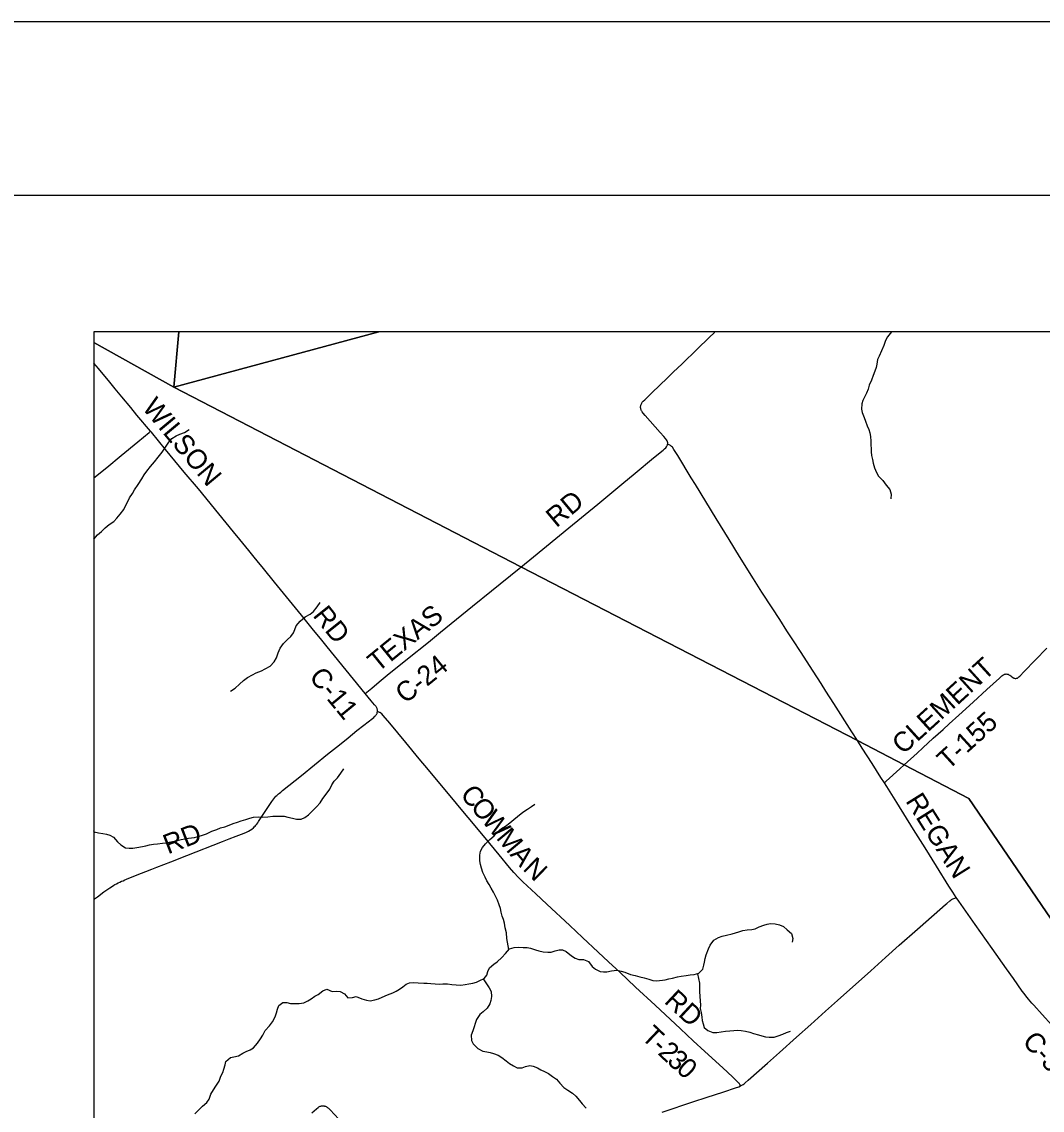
# Model space of a CAD drawing. Extents: x 0 to 34, y 0 to 22.
# Drawn here: x 24.58 to 27.52, y 18.863 to 22 of the extents above; entities that cross this region are included whole.
import ezdxf

# ---------------------------------------------------------------- set-up
doc = ezdxf.new("R2010")
doc.units = 0
for name, color, linetype in [('GM_X_Corporation', 7, 'Continuous'), ('GM_X_County_Road', 7, 'Continuous'), ('GM_X_County_Road_Text', 7, 'Continuous'), ('GM_X_Minor_River', 7, 'Continuous'), ('GM_X_Township_Road', 7, 'Continuous'), ('GM_X_Township_Road_Text', 7, 'Continuous'), ('SH_Border', 7, 'Continuous'), ('SH_Cut_Line', 7, 'Continuous')]:
    doc.layers.add(name, color=color, linetype=linetype)

msp = doc.modelspace()

# ---------------------------------------------------------------- linework, layer by layer
at = {"layer": 'GM_X_Corporation'}
for points in [[(31.5875, 16.2767), (31.5875, 21.1059), (24.7875, 21.1059), (24.7875, 14.3059), (28.9316, 14.3059), (29.0116, 14.3654), (30.2271, 15.2782), (30.4064, 15.4161), (30.5426, 15.5161)], [(25.0317, 21.1059), (24.7875, 21.1059), (24.7875, 21.0754), (25.0178, 20.9472)], [(31.5875, 16.2767), (31.5875, 21.1059), (25.6086, 21.1059), (25.0178, 20.9472), (26.0175, 20.4289), (26.9873, 19.9283), (27.122, 19.8586), (27.3085, 19.7612), (27.7955, 19.0474), (28.3618, 18.3058), (29.4482, 16.7745), (29.7308, 16.376), (30.2965, 15.5727), (30.4064, 15.4161), (30.5426, 15.5161)], [(25.6086, 21.1059), (25.0317, 21.1059), (25.0178, 20.9472)], [(24.7875, 21.0754), (24.7875, 14.3059), (28.9316, 14.3059), (29.0116, 14.3654), (30.2271, 15.2782), (30.4064, 15.4161), (30.2965, 15.5727), (29.7308, 16.376), (29.4482, 16.7745), (28.3618, 18.3058), (27.7955, 19.0474), (27.3085, 19.7612), (27.122, 19.8586), (26.9873, 19.9283), (26.0175, 20.4289), (25.0178, 20.9472)]]:
    msp.add_lwpolyline(points, close=True, dxfattribs=at)
at = {"layer": 'GM_X_County_Road'}
for points in [[(26.4403, 20.7819), (26.4406, 20.7839), (26.4406, 20.785), (26.4406, 20.7868), (26.4403, 20.7885), (26.4398, 20.7904), (26.4388, 20.7925), (26.4373, 20.7948), (26.4344, 20.7987), (26.4295, 20.8043), (26.4188, 20.8165), (26.4049, 20.8324), (26.3755, 20.8652), (26.3701, 20.8714), (26.3672, 20.8755), (26.3662, 20.8772), (26.3652, 20.8788), (26.3646, 20.8803), (26.364, 20.8817), (26.3632, 20.8837), (26.3629, 20.8855), (26.3626, 20.888), (26.3626, 20.8895), (26.3626, 20.8913), (26.3629, 20.8931), (26.3632, 20.8944), (26.3639, 20.8969), (26.3648, 20.8986), (26.3657, 20.9004), (26.3665, 20.9017), (26.3674, 20.9031), (26.3699, 20.906), (26.3744, 20.9105), (26.3872, 20.9231), (26.3975, 20.933), (26.4151, 20.9496), (26.4415, 20.9751), (26.4565, 20.9899), (26.4822, 21.0143), (26.5259, 21.0567), (26.5596, 21.0897), (26.5753, 21.1048), (26.5764, 21.1059)], [(24.9507, 20.8198), (24.9115, 20.8663), (24.8935, 20.8885), (24.868, 20.919), (24.8491, 20.9421), (24.8336, 20.9607), (24.8008, 21.0005), (24.7875, 21.0162)], [(25.5692, 20.0641), (25.5357, 20.1054), (25.4598, 20.1983), (25.444, 20.2175), (25.4159, 20.2515), (25.3853, 20.2899), (25.3509, 20.3316), (25.3078, 20.3846), (25.276, 20.4236), (25.2581, 20.4459), (25.2495, 20.4565), (25.2336, 20.4756), (25.2075, 20.5073), (25.1892, 20.53), (25.1473, 20.5816), (25.0887, 20.6533), (25.0479, 20.7018), (25.0345, 20.7181), (24.9936, 20.7673), (24.9532, 20.8169), (24.9507, 20.8198)], [(26.0177, 20.4283), (26.0539, 20.4581), (26.1561, 20.5412), (26.239, 20.6096), (26.3086, 20.6669), (26.3472, 20.6991), (26.3998, 20.7427), (26.4271, 20.7653), (26.4317, 20.7693), (26.4348, 20.7723), (26.4371, 20.7752), (26.4381, 20.7768), (26.4389, 20.7783), (26.4398, 20.7804), (26.4403, 20.7819)], [(26.9875, 19.9278), (26.9711, 19.9535), (26.9193, 20.0347), (26.896, 20.0707), (26.8823, 20.0922), (26.8593, 20.1284), (26.8234, 20.1844), (26.8035, 20.2152), (26.784, 20.2447), (26.7632, 20.2772), (26.7412, 20.311), (26.7117, 20.3563), (26.6877, 20.3941), (26.6478, 20.4585), (26.6177, 20.5079), (26.5806, 20.5682), (26.5205, 20.6662), (26.5084, 20.6857), (26.4697, 20.7495), (26.4584, 20.7674), (26.454, 20.7739), (26.452, 20.7761), (26.4498, 20.7777), (26.4482, 20.7788), (26.4469, 20.7794), (26.445, 20.7801), (26.4403, 20.7819)], [(25.5692, 20.0641), (25.5881, 20.0795), (25.609, 20.0974), (25.632, 20.1163), (25.6906, 20.1634), (25.7511, 20.2121), (25.7857, 20.2404), (25.8784, 20.3156), (25.9325, 20.3593), (26.0122, 20.4238), (26.0177, 20.4283)], [(25.6041, 20.0116), (25.6042, 20.0168), (25.6038, 20.0186), (25.6032, 20.0202), (25.6024, 20.0223), (25.6014, 20.024), (25.6004, 20.0255), (25.5994, 20.027), (25.5962, 20.0315), (25.5867, 20.0424), (25.5692, 20.0641)], [(24.7875, 19.4705), (24.7919, 19.4738), (24.7974, 19.4781), (24.816, 19.4916), (24.8333, 19.5037), (24.8412, 19.5088), (24.8449, 19.511), (24.8482, 19.5129), (24.8529, 19.5154), (24.857, 19.5176), (24.862, 19.5199), (24.8672, 19.5224), (24.8713, 19.5241), (24.8764, 19.5263), (24.8815, 19.5285), (24.9069, 19.5387), (24.9542, 19.5574), (24.9686, 19.5632), (25.0092, 19.579), (25.0548, 19.597), (25.1584, 19.6374), (25.1776, 19.6446), (25.1974, 19.6521), (25.213, 19.6583), (25.2255, 19.6635), (25.2289, 19.6651), (25.2328, 19.667), (25.2381, 19.6701), (25.2422, 19.6728), (25.247, 19.6765), (25.2495, 19.679), (25.2518, 19.6813), (25.2543, 19.6843), (25.2565, 19.6869), (25.2594, 19.691), (25.2618, 19.6945), (25.2903, 19.7383), (25.2999, 19.7528), (25.3054, 19.7603), (25.3086, 19.7639), (25.3117, 19.7674), (25.3146, 19.7701), (25.3164, 19.7717), (25.319, 19.7742), (25.322, 19.7767), (25.3256, 19.7797), (25.331, 19.7841), (25.3852, 19.8278), (25.4608, 19.8884), (25.4946, 19.9158), (25.5197, 19.9362), (25.5453, 19.9568), (25.5653, 19.9727), (25.5897, 19.9919), (25.5935, 19.995), (25.5972, 19.9983), (25.5986, 19.9997), (25.6001, 20.0014), (25.6016, 20.0033), (25.6024, 20.0047), (25.6032, 20.0065), (25.6039, 20.0087), (25.6041, 20.0116)], [(27.0648, 19.8064), (27.0549, 19.822), (27.0293, 19.8624), (27.0012, 19.9064), (26.9875, 19.9278)], [(27.2719, 19.4757), (27.2618, 19.4911), (27.2504, 19.5088), (27.2148, 19.5665), (27.1823, 19.6187), (27.1492, 19.6713), (27.1006, 19.7494), (27.072, 19.7953), (27.0648, 19.8064)], [(27.6884, 18.9512), (27.6794, 18.9612), (27.6446, 19), (27.6128, 19.035), (27.5895, 19.0608), (27.5681, 19.0842), (27.5474, 19.1073), (27.5192, 19.138), (27.4952, 19.165), (27.4895, 19.1714), (27.4847, 19.177), (27.4802, 19.1823), (27.4762, 19.1874), (27.4722, 19.1925), (27.4673, 19.1992), (27.4623, 19.206), (27.4369, 19.242), (27.4167, 19.2704), (27.3758, 19.3283), (27.3261, 19.3981), (27.2789, 19.4652), (27.2719, 19.4757)]]:
    msp.add_lwpolyline(points, dxfattribs=at)
at = {"layer": 'GM_X_Minor_River'}
for points in [[(27.0857, 21.1059), (27.0812, 21.1017), (27.0742, 21.0915), (27.068, 21.0809), (27.0629, 21.0673), (27.0503, 21.0363), (27.0453, 21.0261), (27.0428, 21.0128), (27.0416, 21.0033), (27.0376, 20.9931), (27.0322, 20.9807), (27.0274, 20.967), (27.0212, 20.9527), (27.018, 20.9409), (27.0137, 20.9296), (27.009, 20.9197), (27.0031, 20.9084), (26.9996, 20.8986), (26.9987, 20.8834), (27.0008, 20.8739), (27.0064, 20.8597), (27.01, 20.8491), (27.0152, 20.8353), (27.02, 20.8246), (27.0233, 20.8151), (27.0251, 20.8041), (27.0257, 20.7915), (27.0259, 20.7797), (27.0266, 20.7698), (27.0265, 20.7603), (27.0279, 20.7501), (27.0304, 20.7383), (27.0322, 20.728), (27.0362, 20.7146), (27.0425, 20.7009), (27.0477, 20.6898), (27.0605, 20.6775), (27.0698, 20.6645), (27.0807, 20.6514), (27.0847, 20.6385), (27.0834, 20.6252)], [(24.9722, 20.7446), (24.9838, 20.7593), (24.9942, 20.7736), (25.0031, 20.788), (25.012, 20.7985), (25.0247, 20.806), (25.0346, 20.8108), (25.0488, 20.8163), (25.0622, 20.8249)], [(24.7875, 20.5086), (24.7983, 20.5209), (24.8091, 20.5306), (24.8195, 20.5415), (24.831, 20.5505), (24.8448, 20.5595), (24.854, 20.5693), (24.8629, 20.5806), (24.8734, 20.5945), (24.8796, 20.6066), (24.8854, 20.6168), (24.8901, 20.6274), (24.899, 20.6406), (24.9049, 20.6511), (24.9153, 20.6666), (24.9254, 20.6828), (24.9324, 20.6938), (24.9397, 20.7043), (24.9502, 20.7179), (24.9618, 20.7311), (24.9722, 20.7446)], [(25.1813, 20.0705), (25.1944, 20.0791), (25.2074, 20.0903), (25.2186, 20.1009), (25.2297, 20.1099), (25.2447, 20.118), (25.255, 20.1229), (25.2699, 20.1295), (25.281, 20.1351), (25.2952, 20.1425), (25.3064, 20.1546), (25.3134, 20.1667), (25.3185, 20.1814), (25.324, 20.1947), (25.3333, 20.2075), (25.3452, 20.2195), (25.3548, 20.2285), (25.3625, 20.2387), (25.3665, 20.2485), (25.37, 20.2591), (25.3816, 20.2719), (25.3958, 20.2843), (25.4104, 20.2929), (25.4204, 20.3), (25.4308, 20.3131), (25.4389, 20.326)], [(24.7884, 19.665), (24.8005, 19.6626), (24.8134, 19.6601), (24.8233, 19.6581), (24.8335, 19.6557), (24.8437, 19.6492), (24.8554, 19.6365), (24.8651, 19.6273), (24.8783, 19.6188), (24.889, 19.6179), (24.8993, 19.6178), (24.9115, 19.6199), (24.9275, 19.6228), (24.937, 19.6249), (24.9477, 19.6275), (24.9591, 19.6293), (24.9706, 19.6303), (24.985, 19.632), (24.9957, 19.633), (25.0087, 19.6359), (25.0186, 19.6385), (25.0384, 19.6428), (25.0495, 19.6453), (25.0598, 19.6467), (25.0769, 19.6488), (25.0911, 19.6525), (25.1006, 19.6554), (25.1117, 19.6591), (25.1277, 19.6665), (25.1415, 19.672), (25.1526, 19.6761), (25.1648, 19.6797), (25.177, 19.6842), (25.1885, 19.6886), (25.2011, 19.693), (25.2122, 19.6971), (25.2248, 19.7003), (25.2366, 19.7048), (25.2473, 19.7073), (25.2629, 19.7079), (25.2736, 19.7074), (25.2888, 19.7087), (25.3025, 19.7097), (25.3124, 19.7104), (25.3219, 19.7103), (25.3356, 19.7101), (25.3466, 19.7077), (25.3599, 19.7041), (25.3713, 19.7017), (25.3842, 19.7012), (25.3953, 19.7064), (25.4061, 19.7139), (25.4176, 19.7255), (25.4292, 19.7368), (25.4396, 19.7488), (25.4473, 19.7609), (25.457, 19.7733), (25.4671, 19.7884), (25.4725, 19.8009), (25.4795, 19.8107), (25.4888, 19.8209), (25.4992, 19.8337), (25.5073, 19.8469)], [(25.983, 19.3259), (25.9788, 19.3469), (25.977, 19.3576), (25.976, 19.3739), (25.9728, 19.3884), (25.9703, 19.4017), (25.9678, 19.412), (25.9641, 19.4223), (25.9612, 19.433), (25.9586, 19.4436), (25.955, 19.4547), (25.9498, 19.4677), (25.9446, 19.4799), (25.9387, 19.491), (25.9316, 19.5024), (25.926, 19.5131), (25.9197, 19.5242), (25.9148, 19.5346), (25.9081, 19.5479), (25.9037, 19.5601), (25.9012, 19.5708), (25.8994, 19.5818), (25.8992, 19.5974), (25.9017, 19.6088), (25.9067, 19.6201), (25.9156, 19.6303), (25.9283, 19.6427), (25.9406, 19.6539), (25.9495, 19.6641), (25.9622, 19.6746), (25.9737, 19.6813), (25.9856, 19.6914), (25.9971, 19.7008), (26.0083, 19.709), (26.0232, 19.7214), (26.037, 19.73), (26.0478, 19.7382), (26.0581, 19.7449)], [(24.7875, 19.6612), (24.7891, 19.6627), (24.7875, 19.6682)], [(25.7928, 19.2271), (25.8061, 19.2269), (25.8183, 19.2249), (25.8312, 19.2236), (25.8449, 19.2234), (25.8574, 19.2248), (25.8677, 19.2266), (25.8796, 19.2287), (25.8895, 19.232), (25.8994, 19.2361), (25.9121, 19.2424), (25.9194, 19.2522), (25.9226, 19.2624), (25.9273, 19.2734), (25.9396, 19.2839), (25.9495, 19.2899), (25.9623, 19.3026), (25.973, 19.3139), (25.9846, 19.3279), (25.998, 19.3315), (26.0117, 19.3321), (26.0242, 19.3316), (26.0356, 19.3315), (26.0451, 19.3295), (26.0599, 19.3247), (26.0698, 19.322), (26.0815, 19.3195), (26.0948, 19.3183), (26.1044, 19.3185), (26.1162, 19.3222), (26.128, 19.3247), (26.1375, 19.3246), (26.1477, 19.3203), (26.1636, 19.3072), (26.1738, 19.301), (26.1844, 19.2971), (26.1981, 19.2973), (26.2125, 19.2911), (26.2226, 19.2773), (26.2327, 19.2696), (26.2463, 19.2626), (26.2558, 19.261), (26.2654, 19.2616), (26.2787, 19.2641), (26.294, 19.2663), (26.3065, 19.2638), (26.3167, 19.2603), (26.3334, 19.254), (26.3466, 19.2505), (26.3607, 19.2473), (26.3732, 19.2445), (26.3865, 19.2401), (26.3975, 19.2366), (26.4096, 19.2357), (26.4332, 19.2385), (26.4443, 19.241), (26.4546, 19.2436), (26.4687, 19.2468), (26.4794, 19.2486), (26.4939, 19.2507), (26.5057, 19.2525), (26.5171, 19.2539), (26.5301, 19.2572), (26.5417, 19.2692), (26.5445, 19.2802), (26.5465, 19.2896), (26.5489, 19.2999), (26.5517, 19.3105), (26.558, 19.3275), (26.5634, 19.3388), (26.5739, 19.3528), (26.5865, 19.3606), (26.5976, 19.3639), (26.6098, 19.3668), (26.6262, 19.3712), (26.6358, 19.3737), (26.6457, 19.3771), (26.6568, 19.3807), (26.6694, 19.3825), (26.6831, 19.3839), (26.693, 19.3856), (26.7037, 19.3908), (26.7171, 19.3956), (26.7274, 19.3989), (26.7369, 19.4011), (26.7498, 19.4002), (26.7627, 19.3974), (26.7745, 19.3919), (26.785, 19.3823), (26.7971, 19.3716), (26.8011, 19.3578), (26.7994, 19.3468)], [(25.9088, 19.2408), (25.9187, 19.2272), (25.9266, 19.2153), (25.9318, 19.2046), (25.9331, 19.1905), (25.9315, 19.1788), (25.9283, 19.1689), (25.9205, 19.1565), (25.909, 19.146), (25.8994, 19.1381), (25.8901, 19.1245), (25.8861, 19.1128), (25.883, 19.103), (25.879, 19.0916), (25.8739, 19.0787), (25.8753, 19.0631), (25.8805, 19.0536), (25.8933, 19.0409), (25.908, 19.0328), (25.9194, 19.0304), (25.9293, 19.0287), (25.9391, 19.026), (25.9524, 19.0209), (25.9626, 19.0147), (25.975, 19.0047), (25.9852, 18.9969), (25.9965, 18.9904), (26.0067, 18.9845), (26.0216, 18.9844), (26.0311, 18.9885), (26.0433, 18.9917), (26.0532, 18.9897), (26.0653, 18.9847), (26.0751, 18.9792), (26.0861, 18.9738), (26.0971, 18.968), (26.1084, 18.9599), (26.1201, 18.9517), (26.1302, 18.9402), (26.1411, 18.9283), (26.1528, 18.9202), (26.1664, 18.9121), (26.1762, 18.9032), (26.1863, 18.891), (26.1938, 18.8806), (26.2058, 18.868)], [(26.526, 19.2561), (26.5292, 19.2427), (26.5321, 19.229), (26.5319, 19.2172), (26.5321, 19.2047), (26.5327, 19.1903), (26.5337, 19.1781), (26.5347, 19.1652), (26.5346, 19.1557), (26.5371, 19.1439), (26.5389, 19.1309), (26.5403, 19.1214), (26.5428, 19.1115), (26.5461, 19.1012), (26.5559, 19.0924), (26.571, 19.0869), (26.5825, 19.0867), (26.595, 19.0885), (26.6072, 19.0903), (26.6198, 19.0916), (26.6312, 19.0927), (26.6423, 19.0929), (26.6521, 19.092), (26.6647, 19.0904), (26.6772, 19.0872), (26.6878, 19.0837), (26.7026, 19.0797), (26.7121, 19.0769), (26.7227, 19.0742), (26.7329, 19.0729), (26.7478, 19.0735), (26.7593, 19.0772), (26.7719, 19.0816), (26.7833, 19.0868), (26.794, 19.0908)], [(25.0779, 18.8522), (25.0887, 18.8631), (25.1007, 18.8743), (25.1126, 18.8844), (25.1199, 18.8946), (25.1247, 18.9086), (25.132, 18.9218), (25.1383, 18.9316), (25.1479, 18.9463), (25.1531, 18.9603), (25.1593, 18.9713), (25.1621, 18.9811), (25.1656, 18.9932), (25.168, 19.0027), (25.1807, 19.0147), (25.1906, 19.0165), (25.204, 19.0198), (25.2166, 19.0269), (25.2266, 19.0321), (25.2373, 19.0369), (25.2473, 19.0425), (25.2588, 19.056), (25.267, 19.0685), (25.2743, 19.0786), (25.281, 19.0919), (25.2937, 19.1058), (25.3018, 19.1178), (25.3096, 19.1318), (25.3139, 19.1432), (25.3167, 19.1534), (25.3203, 19.164), (25.3322, 19.1726), (25.3432, 19.1732), (25.3542, 19.1701), (25.3698, 19.1706), (25.3793, 19.1705), (25.3919, 19.1719), (25.4034, 19.1775), (25.413, 19.1835), (25.4237, 19.1909), (25.4333, 19.1958), (25.4467, 19.2066), (25.4586, 19.2111), (25.4741, 19.2044), (25.4851, 19.2054), (25.4973, 19.2049), (25.509, 19.198), (25.5191, 19.1868), (25.5328, 19.1874), (25.5428, 19.1904), (25.5598, 19.1841), (25.5731, 19.1794), (25.5833, 19.1781), (25.5971, 19.1806), (25.6074, 19.1835), (25.6181, 19.1887), (25.633, 19.1947), (25.6483, 19.2013), (25.6579, 19.2062), (25.6678, 19.2114), (25.6774, 19.2185), (25.6874, 19.2263), (25.697, 19.23), (25.7091, 19.2303), (25.7221, 19.2297), (25.738, 19.2288), (25.7479, 19.2287), (25.7586, 19.2282), (25.7707, 19.2269), (25.7821, 19.2257), (25.7928, 19.2271)]]:
    msp.add_lwpolyline(points, dxfattribs=at)
at = {"layer": 'GM_X_Township_Road'}
for points in [[(24.7875, 20.6853), (24.8243, 20.7153), (24.8656, 20.7493), (24.9144, 20.7896), (24.9465, 20.8163), (24.9507, 20.8198)], [(27.1222, 19.8581), (27.1594, 19.8922), (27.176, 19.9072), (27.2056, 19.9347), (27.2338, 19.9601), (27.2518, 19.9763), (27.2793, 20.0015), (27.3207, 20.039), (27.3604, 20.0748), (27.3965, 20.1082), (27.4006, 20.112), (27.4034, 20.1145), (27.4057, 20.1162), (27.4079, 20.1177), (27.4096, 20.1187), (27.4114, 20.1194), (27.4134, 20.1198), (27.4151, 20.12), (27.4174, 20.1199), (27.4192, 20.1196), (27.4212, 20.119), (27.4234, 20.118), (27.4261, 20.1164), (27.4291, 20.1143), (27.4325, 20.1115), (27.4365, 20.1087), (27.4379, 20.108), (27.4393, 20.1075), (27.4412, 20.1072), (27.4424, 20.1072), (27.4438, 20.1071), (27.4454, 20.1075), (27.4468, 20.1078), (27.448, 20.1084), (27.4494, 20.1093), (27.4524, 20.1116), (27.4547, 20.1136), (27.4675, 20.1272), (27.4996, 20.1602), (27.5331, 20.1943)], [(26.6505, 18.9328), (26.6499, 18.9342), (26.6489, 18.9363), (26.6479, 18.9383), (26.6472, 18.9394), (26.6459, 18.9409), (26.627, 18.9589), (26.5992, 18.9846), (26.5479, 19.0316), (26.514, 19.0627), (26.4772, 19.0971), (26.4041, 19.1654), (26.3483, 19.2175), (26.3023, 19.2602), (26.2702, 19.2905), (26.2407, 19.3181), (26.1953, 19.3605), (26.1584, 19.3947), (26.0921, 19.4566), (26.0609, 19.486), (26.0233, 19.5213), (26.0109, 19.5335), (25.9973, 19.548), (25.9851, 19.5622), (25.9546, 19.599), (25.9277, 19.6316), (25.8861, 19.6819), (25.8457, 19.7299), (25.8184, 19.7629), (25.7747, 19.8154), (25.7512, 19.8436), (25.7245, 19.8755), (25.6862, 19.9221), (25.6398, 19.978), (25.621, 20.0004), (25.6167, 20.0052), (25.6145, 20.007), (25.6137, 20.0076), (25.6122, 20.0086), (25.6106, 20.0094), (25.6085, 20.0102), (25.6041, 20.0116)], [(27.0648, 19.8064), (27.0701, 19.8112), (27.1095, 19.8464), (27.1222, 19.8581)], [(26.6505, 18.9328), (26.6527, 18.9339), (26.6562, 18.9357), (26.6579, 18.9368), (26.6607, 18.9387), (26.6639, 18.9411), (26.6728, 18.9488), (26.7284, 18.9985), (26.7627, 19.0291), (26.8113, 19.0727), (26.853, 19.11), (26.8951, 19.1477), (26.9302, 19.1793), (27.0256, 19.2646), (27.0677, 19.3023), (27.1076, 19.3379), (27.1599, 19.3846), (27.1678, 19.3916), (27.2412, 19.4559), (27.2444, 19.4587), (27.2531, 19.466), (27.2564, 19.4685), (27.2571, 19.469), (27.2582, 19.4697), (27.2597, 19.4705), (27.262, 19.4715), (27.2677, 19.474), (27.2719, 19.4757)], [(26.4249, 18.8574), (26.5158, 18.8873), (26.5512, 18.8991), (26.6026, 18.9157), (26.6362, 18.9268), (26.6454, 18.9304), (26.6505, 18.9328)], [(25.4158, 18.8551), (25.4287, 18.8669), (25.4331, 18.8704), (25.4354, 18.8719), (25.4376, 18.8731), (25.4396, 18.874), (25.4411, 18.8745), (25.4428, 18.8749), (25.444, 18.8751), (25.4456, 18.8752), (25.4475, 18.8753), (25.4493, 18.8751), (25.4507, 18.875), (25.4521, 18.8747), (25.4539, 18.8741), (25.4547, 18.8738), (25.4562, 18.8732), (25.4577, 18.8723), (25.4598, 18.8711), (25.4618, 18.8696), (25.4637, 18.868), (25.4655, 18.8664), (25.4686, 18.8634), (25.4934, 18.8372)]]:
    msp.add_lwpolyline(points, dxfattribs=at)
at = {"layer": 'SH_Border'}
msp.add_lwpolyline([(1.5, 21.5), (33.5, 21.5), (33.5, 0.5), (1.5, 0.5)], close=True, dxfattribs=at)
at = {"layer": 'SH_Cut_Line'}
msp.add_lwpolyline([(0, 0), (34, 0), (34, 22), (0, 22)], close=True, dxfattribs=at)

# ---------------------------------------------------------------- texts
at = {"layer": 'GM_X_County_Road_Text'}
for s, rotation, p in [('WILSON', 309.7838, (24.9244, 20.8866)), ('RD', 39.8666, (26.1198, 20.5399)), ('RD', 308.7371, (25.4162, 20.2881)), ('TEXAS', 39.1554, (25.6054, 20.1232)), ('C-24', 38.9265, (25.6847, 20.0322)), ('C-11', 309.4103, (25.405, 20.1106)), ('REGAN', 302.0453, (27.1244, 19.7542)), ('RD', 21.2508, (25.0007, 19.5998)), ('C-31', 312.0926, (27.4598, 19.0587))]:
    msp.add_text(s, height=0.05682, rotation=rotation, dxfattribs=at).set_placement(p)
at = {"layer": 'GM_X_Township_Road_Text'}
for s, height, rotation, p in [('CLEMENT', 0.05682, 42.3416, (27.1187, 19.8857)), ('T-155', 0.05682, 42.4226, (27.249, 19.841)), ('C', 0.0568, 309.7796, (25.8403, 19.7716)), ('O', 0.0568, 309.7851, (25.8701, 19.7357)), ('W', 0.0568, 309.7829, (25.9021, 19.6973)), ('M', 0.0568, 309.7799, (25.9443, 19.6467)), ('A', 0.0568, 310.3433, (25.9841, 19.5988)), ('N', 0.0568, 315.9467, (26.0206, 19.5563)), ('RD', 0.05682, 317.0941, (26.4281, 19.1739)), ('T', 0.0568, 316.4669, (26.3616, 19.071)), ('-', 0.0568, 316.5451, (26.3925, 19.0417)), ('2', 0.0568, 316.8554, (26.4097, 19.0254)), ('3', 0.0568, 317.4312, (26.4357, 19.0011)), ('0', 0.0568, 318.503, (26.4623, 18.9766))]:
    msp.add_text(s, height=height, rotation=rotation, dxfattribs=at).set_placement(p)

doc.saveas('drawing.dxf')
